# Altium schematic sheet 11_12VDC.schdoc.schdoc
size 302 x 215 mm; Symbol: Sheet_A4; Device: Sheet_A4; @Project Name: Avaota Pi A; Company: YuzukiHD; Version: 1.0; @Page No: 2; @Page Count: 13; @Update Date: 2024-02-27; Comment: GloomyGhost
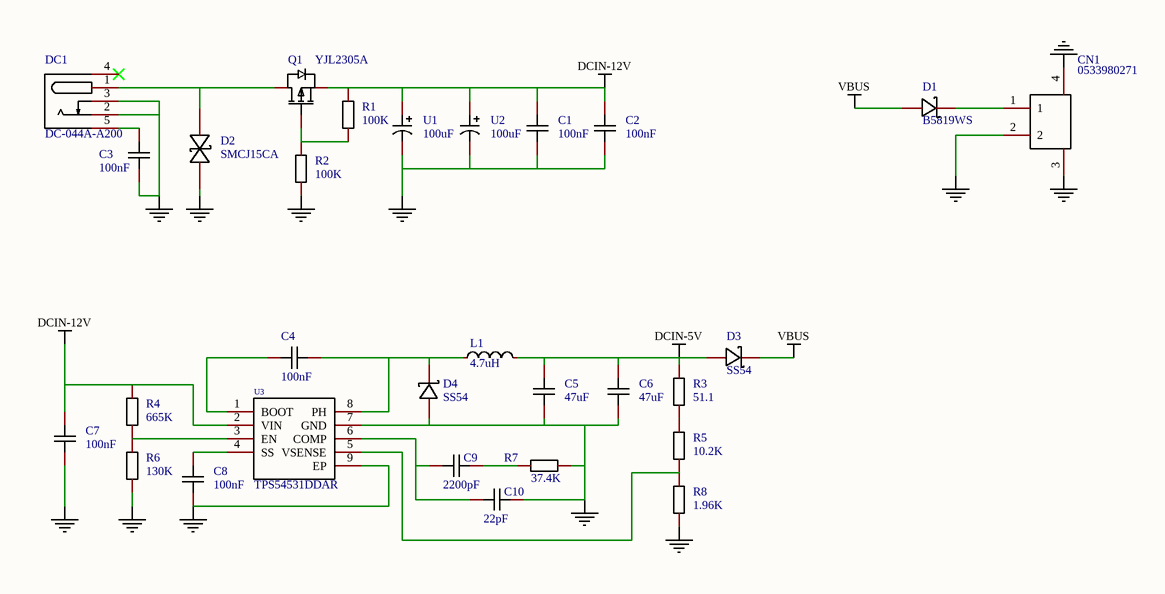
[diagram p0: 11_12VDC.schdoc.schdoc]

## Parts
C1  100nF  [C0603-NSK]
C2  100nF  [C0603-NSK]
C3  100nF  [C0603-NSK]
C4  100nF  [c0402-nsk]
C5  47uF  [C0805 NSK]
C6  47uF  [C0805 NSK]
C7  100nF  [C0603-NSK]
C8  100nF  [C0603-NSK]
C9  2200pF  [c0402-nsk]
C10  22pF  [c0402-nsk]
CN1  0533980271  [CONN-SMD_2P-P1.25_053398-0X71]
D1  B5819WS  [SOD-323_L1.8-W1.3-LS2.5-RD]
D2  SMCJ15CA  [SMC_L6.9-W5.9-LS7.9-BI]
D3  SS54  [SMA_L4.4-W2.8-LS5.4-R-RD]
D4  SS54  [SMA_L4.4-W2.8-LS5.4-R-RD]
DC1  DC-044A-A200  [DC-IN-TH_DC-044A-20A]
L1  4.7uH  [IND-SMD_L7.0-W6.6]
Q1  YJL2305A  [SOT-23-3_L2.9-W1.3-P1.90-LS2.4-BR]
R1  100K  [R0603 NSK]
R2  100K  [R0603 NSK]
R3  51.1  [R0402-NSK]
R4  665K  [R0402-NSK]
R5  10.2K  [R0402-NSK]
R6  130K  [R0402-NSK]
R7  37.4K  [R0402-NSK]
R8  1.96K  [R0402-NSK]
U1  100uF  [CAP-SMD_BD6.3-L6.6-W6.6-LS7.6-RD]
U2  100uF  [CAP-SMD_BD6.3-L6.6-W6.6-LS7.6-RD]
U3  TPS54531DDAR  [SOIC-8_L5.0-W4.0-P1.27-LS6.0-BL-EP2.0]

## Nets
DCIN-5V: C5.2 C6.2 D3.1(A) L1.2 R3.2
DCIN-12V: C1.2 C2.2 C7.2 Q1.2(S) R1.2 R4.2 U1.1 U2.1 U3.2(VIN)
NetC1_1: C1.1 C2.1 C3.1 C5.1 C6.1 C7.1 C8.1 C10.2 CN1.2 CN1.3 CN1.4 D2.1 D4.1(A) DC1.2 DC1.3 R2.1 R6.1 R7.2 R8.1 U1.2 U2.2 U3.7(GND) U3.9(EP)
VBUS: D1.2(A) D3.2(K)
NetC3_2: C3.2 DC1.5
NetC4_1: C4.1 U3.1(BOOT)
NetC4_2: C4.2 D4.2(K) L1.1 U3.8(PH)
NetC8_2: C8.2 U3.4(SS)
NetC9_1: C9.1 C10.1 U3.6(COMP)
NetC9_2: C9.2 R7.1
NetCN1_1: CN1.1 D1.1(K)
NetD2_2: D2.2 DC1.1 Q1.3(D)
NetQ1_1: Q1.1(G) R1.1 R2.2
NetR3_1: R3.1 R5.2
NetR4_1: R4.1 R6.2 U3.3(EN)
NetR5_1: R5.1 R8.2 U3.5(VSENSE)

Not connected (* = marked no-connect by the designer): DC1 4*

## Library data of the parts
C1-C3 C7 C8 = CAP_0603: Symbol: CapAcitance; Convert to PCB: yes
C4 C9 C10 = CAP_0402: Symbol: CapAcitance; Convert to PCB: yes
C5 C6 = CAP_0805: Symbol: CapAcitance; Convert to PCB: yes
CN1 = 0533980271: Manufacturer: MOLEX; Add into BOM: yes; Pins Structure: 1x2P; Pitch: 1.25mm; Number of PINs Per Row: 2; Description: 插针结构:1x2P;间距:1.25mm;安装方式:立贴;参考系列:-;总PIN数:2P;排数:1;每排PIN数:2;行距:-;额定电流:-;触头材质:磷青铜;触头镀层:锡;工作温度范围:-;
D1 = B5819WS_C22624: Manufacturer: CJ(江苏长电/长晶); Add into BOM: yes; Forward Voltage (Vf@If): 600mV@1A; Reverse Voltage (Vr): 40V; Average Rectified Current (Io): 1A; Description: 正向压降(Vf):600mV@1A;直流反向耐压(Vr):40V;平均整流电流(Io):1A;
D2 = SMCJ15CA_C438202: Manufacturer: 晶导微电子; Add into BOM: yes
D3 D4 = SS54_C22452: Manufacturer: MDD; Add into BOM: yes; Forward Voltage (Vf@If): 550mV@5A; Reverse Voltage (Vr): 40V; Average Rectified Current (Io): 5A; Reverse Leakage Current (Ir): 1mA@40V; Description: 正向压降(Vf):550mV@5A;直流反向耐压(Vr):40V;平均整流电流(Io):5A;
DC1 = DC-044A-A200: Manufacturer: XUNPU(讯普); Add into BOM: yes; Connector Type: DC电源插座; Inside Contact Diameter: 2mm; Outside Contact Diameter: 5.9mm; Current Rating (Max): 3A; Voltage Rating (Max): 30V; Description: 连接器类型:DC电源插座;安装方式:弯插;触点内径:2mm;触点外径:5.9mm;额定电流:3A;额定电压:30V;工作温度范围:-20℃~+70℃;
L1 = FXL0630-4R7-M: Manufacturer: cjiang(长江微电); Add into BOM: yes; Tolerance: ±20%; Rated Current: 6A; Saturation Current (Isat): 9A; DC Resistance (DCR): 33mΩ; Type: 一体成型电感; Description: 电感值:4.7uH;精度:±20%;额定电流:6A;饱和电流(Isat):9A;类型:一体成型电感;
Q1 = YJL2305A: Manufacturer: YANGJIE(扬杰); Add into BOM: yes; Type: P沟道; Drain Source Voltage (Vdss): 15V; Continuous Drain Current (Id): 5.6A; Power Dissipation (Pd): 1.2W; Drain Source On Resistance (RDS(on)@Vgs,Id): 25mΩ@4.5V,5.6A; Gate Threshold Voltage (Vgs(th)@Id): 1V@250uA; Total Gate Charge (Qg@Vgs): 7.2nC@4.5V; Input Capacitance (Ciss@Vds): 890pF@9V; Reverse Transfer Capacitance (Crss@Vds): 85pF@9V; Description: 类型:P沟道;漏源电压(Vdss):15V;连续漏极电流(Id):5.6A;功率(Pd):1.2W;导通电阻(RDS(on)@Vgs,Id):25mΩ@4.5V,5.6A;阈值电压(Vgs(th)@Id):1V@250uA;
R1 R2 = Res_0603: Symbol: 电阻; Convert to PCB: yes
R3-R8 = Res_0402: Symbol: 电阻; Convert to PCB: yes
U1 U2 = RVT1H101M0607: Manufacturer: ROQANG(容强); Add into BOM: yes; Tolerance: ±20%; Rated Voltage: 50V; Ripple Current: 229mA@120Hz; φD: 6.3mm; L: 7.7mm; Lifetime @ Temp: 2000hrs@105℃; Description: 容值:100uF;精度:±20%;额定电压:50V;纹波电流:229mA@120Hz;
U3 = TPS54531DDAR: Manufacturer: TI(德州仪器); Add into BOM: yes; Function: 降压型; Output Type: 可调; Input Voltage: 3.5V~28V; Output Voltage: 800mV~26.04V; Output Current (Max): 5A; Switching Frequency: 570kHz; Synchronous Rectification: 否; Number of Outputs: 1; Topology: 降压式; Switch tube (built-in/external): 内置; Description: 功能类型:降压型;输出类型:可调;输入电压:3.5V~28V;输出电压:800mV~26.04V;输出电流(最大值):5A;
